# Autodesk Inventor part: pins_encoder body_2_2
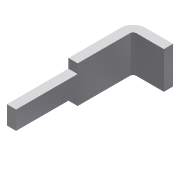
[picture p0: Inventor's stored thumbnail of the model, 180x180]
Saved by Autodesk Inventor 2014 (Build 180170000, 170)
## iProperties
Created: 2015-11
Part Number: pins_encoder body_2_2
Material: Generic
Document SubType Name: Modeling
Designer: Tom
Density: 1 g/cm^3
Appearance: Default
Author: Tom
d2: 0.015 in
d3: 0.090 in
d4: 0.005 in
d6: 0.020 in
d7: 0.060 in
d8: 0.00 deg
d9: 0.030 in
d11: 0.015 in
d12: 0.100 in
d14: 0.00 deg
d10: 0.060 in
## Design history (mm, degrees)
derived "pins_encoder body_2.ipt"
